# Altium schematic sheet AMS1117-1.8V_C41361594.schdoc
size 127 x 101 mm
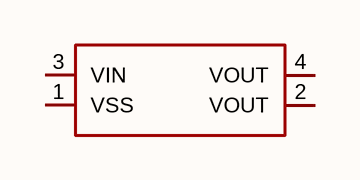
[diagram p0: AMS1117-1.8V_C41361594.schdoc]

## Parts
U?  ams1117-1.8v_c41361594  [SOT-223-3_L6.4-W3.5-P2.30-LS7.0-BR]  (value not drawn)

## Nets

Not connected (* = marked no-connect by the designer): U? 1(VSS) 2(VOUT) 3(VIN) 4(VOUT)

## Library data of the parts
U? = ams1117-1.8v_c41361594: 输出极性:正极;工作电压:12V;输出电压:1.8V;输出电流:1.2A;电源纹波抑制比(PSRR):-;输出类型:固定;; Manufacturer: JSMSEMI(杰盛微); AddInBom: yes; ModelId: 6654433eca7b4e7f8ee05e27058a22e4; ModelTransform: 251.968,275.59,0,90,0,0,-3.937,0,0; Output Configuration: 正极; Voltage - Supply: 12V; Output Voltage: 1.8V; Output Current: 1.2A; Voltage Dropout: 1.3V@(800mA); standby current: 2mA; Output Type: 固定; Number of Outputs: 1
